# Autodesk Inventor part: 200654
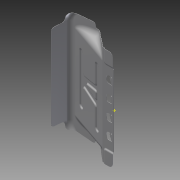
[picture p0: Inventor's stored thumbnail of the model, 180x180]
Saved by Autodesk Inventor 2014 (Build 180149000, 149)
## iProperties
Created: 2007-10
Part Number: 200654
Document SubType Name: Modeling
Designer: TH
Density: 7.85 g/cm^3
Mass: 777.491 g
Surface Area: 2126.93 cm^2
Volume: 99.0434 cm^3
Material: Steel
Description: FRONT TOP SHEILD
Appearance: Steel
Component Category: Lower Component
Author: TH
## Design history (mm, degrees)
sketch "Sketch2"
  geometry: L1 (123, -53.413)-(83.897, -53.413); L2 (83.897, -53.413)-(19.269, -0.007); L3 (-95.471, -64.758)-(-89.791, -0.007); L4 (-89.791, -0.007)-(77.432, -0.007); L5 (-95.471, -64.758)-(-75.394, -64.758); L6 (124.496, -53.413)-(124.496, -54.413); L7 (0, 12.952)-(0, -77.71) reference; L8 (-139.464, 0)-(168.489, 0) reference; L9 (123, -57.413)-(-74.75, -57.413); L10 (-74.75, -57.413)-(-75.394, -64.758); L11 (123, -53.413)-(123, -57.413); 2 further points
  constraints: 18 end point, 4 parallel, 3 perpendicular, 2 point on line, 1 other
  dimensions: "d0" = 89.79065 distance of L3.end point (0, 0); "d1" = 19.26881 distance of L2.end point (0, 0); "d2" = 140.431 deg angle of L2 L4; "d3" = 83.8971 horizontal distance of L1.end point (0, 0); "d4" = 53.41295 distance from line of L1 point (0, 0); "d38" = 20 distance between parallel lines of L10 L3; "d66" = 4 distance from line of L9 L1.end; "d70" = 123 distance from line of point (0, 0) L11
extrude "Extrusion1" new body sketch "Sketch2" stored distance "d6" = 435; taper "d7" = 0 deg
sketch "Sketch3"
  geometry: L1 (0, 0)-(109.059, 0) reference; L2 (0, 0)-(0, 435) reference; L3 (0, 0)-(87.291, 0); L4 (87.291, 0)-(-10, 7.657); L5 (187.801, 317.5)-(199.791, 317.5); L6 (-10, 7.657)-(-10, 0); L7 (-10, 0)-(0, 0); 4 further points
  constraints: 10 end point, 5 point on line, 2 perpendicular, 1 parallel
  dimensions: "d8" = 155 vertical distance of point (0, 62.5) point (89.791, 217.5); "d10" = 2.5 horizontal distance of point (89.791, 217.5) L3.end; "d14" = 100 distance from line of point (89.791, 217.5) L5; "d71" = 10 distance of L6.end L1.start; "d72" = 4.5 deg angle of L1 L4
extrude "Extrusion2" cut sketch "Sketch3" stored distance "d12" = 387.01949; taper "d13" = 0 deg
chamfer "Chamfer1" distance "d16" = 34; stored, may be unused: second distance "d17" = 30, angle "d18" = 45 deg
mirror "Mirror1"
sketch "Sketch4"
  geometry: L1 (83.897, -53.413)-(-71.79, 0); L2 (0, 0)-(-71.79, 0); L3 (130, -53.413)-(83.897, -53.413); L4 (130, -53.413)-(130, 0); L5 (130, 0)-(0, 0)
  constraints: 10 end point, 2 perpendicular, 1 horizontal, 1 parallel
  dimensions: "d19" = 53.41295 distance from line of L2.start L3; "d20" = 83.8971 horizontal distance of L2.start L1.start; "d21" = 71.78981 distance of L2.start L1.end; "d22" = 130 distance from line of L2.start L4
extrude "Extrusion3" cut sketch "Sketch4" stored distance "d23" = 328; taper "d24" = 0 deg
chamfer "Chamfer2" distance "d25" = 29.543; stored, may be unused: second distance "d26" = 15, angle "d27" = 45 deg
chamfer "Chamfer3" distance "d28" = 29.543; stored, may be unused: second distance "d29" = 15, angle "d30" = 45 deg
fillet "Fillet3" dims "d33" = 20
fillet "Fillet8" dims "d40" = 20
fillet "Fillet9" dims "d41" = 20
fillet "Fillet10" dims "d42" = 15, "d58" = 50
fillet "Fillet13" dims "d73" = 2.5
fillet "Fillet14" dims "d74" = 5
shell "Shell1" dims "d43" = 1
sketch "Sketch5"
  geometry: L1 (103, 184)-(6.165, 192.898); L2 (-162.2, 0)-(147.2, 0) reference; L3 (-4.75, 182.94)-(-4.75, 181); L4 (-8.75, 177)-(-46.251, 177); L5 (-49.846, 179.247)-(-50.825, 181.253); L6 (-54.42, 183.5)-(-130, 183.5); L7 (-130, 183.5)-(-130, 220); L8 (-130, 220)-(103, 220); L9 (103, 220)-(103, 184); A1 r 10 centre (5.25, 182.94) between (6.165, 192.898) and (-4.75, 182.94); A2 r 4 centre (-8.75, 181) between (-8.75, 177) and (-4.75, 181); A3 r 4 centre (-46.251, 181) between (-49.846, 179.247) and (-46.251, 177); A4 r 4 centre (-54.42, 179.5) between (-50.825, 181.253) and (-54.42, 183.5); 3 further points
  constraints: 16 end point, 8 point on circle, 8 tangent, 4 centre point, 4 perpendicular, 4 point on line, 2 equal radius, 2 parallel
  dimensions: "d44" = 184 vertical distance of L1.start point (0, 0); "d45" = 103 horizontal distance of point (0, 0) L1.start; "d46" = 5.25 deg angle of L2 L1; "d47" = 4.75 distance from line of L3 point (0, 0); "d48" = 177 distance from line of point (0, 0) L4; "d49" = 44 distance of point (-4.75, 177) point (-48.75, 177); "d50" = 116 deg angle of L4 L5; "d51" = 6.5 distance between parallel lines of L4 L6; "d52" = 130 distance from line of L7 point (0, 0); "d53" = 220 distance between parallel lines of L2 L8; "d54" = 10 radius of A1; "d55" = 4 radius of A2
extrude "Extrusion4" cut sketch "Sketch5" stored distance "d56" = 300; taper "d57" = 0 deg
sketch "Sketch6"
  geometry: L1 (335.141, 0)-(334.789, -51.258) reference; L2 (334.789, -51.258)-(335.036, -15.258); L3 (345.105, -5.327)-(372.105, -5.513); L4 (372.105, -5.513)-(371.789, -51.513); L5 (371.789, -51.513)-(334.789, -51.258); A1 r 10 centre (345.036, -15.327) between (345.105, -5.327) and (335.036, -15.258); 2 further points
  constraints: 8 end point, 3 point on line, 2 perpendicular, 2 point on circle, 2 tangent, 1 centre point, 1 parallel
  dimensions: "d59" = 46 vertical distance of L3.end L4.end; "d60" = 37 horizontal distance of point (335.105, -5.258) L3.end; "d61" = 10 radius of A1
extrude "Extrusion5" cut sketch "Sketch6" distance "d62" = 25; taper "d63" = 0 deg
fillet "Fillet11" dims "d64" = 10
fillet "Fillet12" dims "d65" = 10
mirror "Mirror2"
sketch "Sketch8"
  geometry: L1 (38.269, 329.252)-(0.065, 329.252) reference; L2 (0.065, -37.748)-(38.269, -37.748) reference; L3 (38.269, -37.748)-(38.269, 329.252) reference; L4 (8.269, 329.252)-(8.269, 283.252); L5 (8.269, 283.252)-(37.269, 283.252); L6 (37.269, 283.252)-(37.269, 8.252); L7 (37.269, 8.252)-(8.269, 8.252); L8 (8.269, 8.252)-(8.269, -37.748); 1 further point
  constraints: 10 end point, 3 parallel, 2 perpendicular, 2 point on line, 1 collinear
  dimensions: "d75" = 1 distance between parallel lines of L3 L6; "d76" = 46 distance between parallel lines of L1 L5; "d77" = 46 distance between parallel lines of L2 L7 (= d76); "d78" = 30 distance between parallel lines of L3 L8
extrude "Extrusion7" cut sketch "Sketch8" stored distance "d79" = 275; taper "d80" = 0 deg
sketch "Sketch9"
  geometry: L1 (0.065, -37.748)-(8.269, -37.748) reference; L2 (8.269, -37.748)-(8.269, 8.252) reference; L3 (8.269, 8.252)-(37.269, 8.252) reference; L4 (37.269, 283.252)-(37.269, 8.252) reference; L5 (7.269, -37.748)-(7.269, 9.252); L6 (7.269, 9.252)-(37.269, 9.252); 1 further point
  constraints: 4 end point, 2 point on line, 1 parallel, 1 perpendicular
  dimensions: "d81" = 1 distance between parallel lines of L5 L2; "d82" = 1 distance between parallel lines of L6 L3
extrude "Extrusion8" join sketch "Sketch9" distance "d83" = 3.3941; taper "d84" = 0 deg
sketch "Sketch10"
  geometry: L1 (7.269, 9.252)-(37.269, 9.252) reference; L2 (7.269, -37.748)-(7.269, 9.252) reference; L3 (37.269, 9.252)-(7.269, 9.252); L4 (7.269, 9.252)-(7.269, -37.748); L5 (7.269, -37.748)-(37.269, -37.748); L6 (37.269, -37.748)-(37.269, 9.252); 1 further point
  constraints: 8 end point, 2 parallel, 1 horizontal, 1 perpendicular
extrude "Extrusion9" join sketch "Sketch10" distance "d85" = 1; taper "d86" = 0 deg
mirror "Mirror4"
fillet "Fillet15" dims "d87" = 5, "d88" = 6
fillet "Fillet16" dims "d89" = 4.75, "d90" = 5.75
sketch "Sketch12"
  geometry: L1 (0.307, -1)-(264.202, -1) reference; L2 (315.755, -4.394)-(271.933, -4.394) reference; L3 (315.755, -4.394)-(315.755, -3.394) reference; L4 (315.755, -3.394)-(272.24, -3.394) reference; L5 (0, 0)-(264.51, 0) reference; L6 (-51.245, -3.394)-(-7.73, -3.394) reference; L7 (-51.245, -4.394)-(-51.245, -3.394) reference; L8 (-51.245, -4.394)-(-7.423, -4.394) reference; A1 r 5.75 centre (-7.423, 1.356) between (-7.423, -4.394) and (-3.19, -2.535) reference; A2 r 4.75 centre (0.307, -5.75) between (0.307, -1) and (-3.19, -2.535) reference; A3 r 4.75 centre (264.202, -5.75) between (267.699, -2.535) and (264.202, -1) reference; A4 r 5.75 centre (271.933, 1.356) between (267.699, -2.535) and (271.933, -4.394) reference; A5 r 4.75 centre (272.24, 1.356) between (268.743, -1.859) and (272.24, -3.394) reference; A6 r 5.75 centre (264.51, -5.75) between (268.743, -1.859) and (264.51, 0) reference; A7 r 5.75 centre (0, -5.75) between (0, 0) and (-4.233, -1.859) reference; A8 r 4.75 centre (-7.73, 1.356) between (-7.73, -3.394) and (-4.233, -1.859) reference; 1 further point
extrude "Extrusion11" join sketch "Sketch12" distance "d93" = 2.5; taper "d94" = 0 deg
fillet "Fillet17" dims "d95" = 15
sketch "Sketch13"
  geometry: L1 (34.048, 44.224)-(34.048, 44.224); L2 (34.048, 229.224)-(34.048, 229.224); L3 (26.548, 221.724)-(26.548, 51.724); L4 (127.048, 29.224)-(127.048, 29.224); L5 (134.548, 36.724)-(134.548, 236.724); L6 (127.048, 244.224)-(127.048, 244.224); L7 (53.436, 119.438)-(111.436, 108.284); L8 (53.436, 154.011)-(111.436, 165.164); L9 (41.548, 136.724)-(119.548, 136.724); L10 (119.548, 166.847)-(119.548, 166.724); L11 (119.548, 106.724)-(119.548, 106.602); L12 (119.548, 236.724)-(119.548, 174.985); L13 (119.548, 98.464)-(119.548, 36.724); L14 (41.548, 51.724)-(41.548, 109.618); L15 (41.548, 163.831)-(41.548, 221.724); L16 (157.597, 0)-(0, 0) reference; L17 (68.509, 131.814)-(113.603, 123.142); L18 (119.548, 128.052)-(119.548, 145.396); L19 (113.603, 150.306)-(68.509, 141.634); A1 r 7.5 centre (34.048, 51.724) between (26.548, 51.724) and (34.048, 44.224); A2 r 7.5 centre (34.048, 51.724) between (34.048, 44.224) and (41.548, 51.724); A3 r 7.5 centre (127.048, 36.724) between (119.548, 36.724) and (127.048, 29.224); A4 r 7.5 centre (127.048, 36.724) between (127.048, 29.224) and (134.548, 36.724); A5 r 7.5 centre (127.048, 236.724) between (127.048, 244.224) and (119.548, 236.724); A6 r 7.5 centre (127.048, 236.724) between (134.548, 236.724) and (127.048, 244.224); A7 r 7.5 centre (34.048, 221.724) between (41.548, 221.724) and (34.048, 229.224); A8 r 7.5 centre (34.048, 221.724) between (34.048, 229.224) and (26.548, 221.724); A9 r 10 centre (51.548, 109.618) between (53.436, 119.438) and (41.548, 109.618); A10 r 10 centre (51.548, 163.831) between (41.548, 163.831) and (53.436, 154.011); A11 r 10 centre (109.548, 98.464) between (119.548, 98.464) and (111.436, 108.284); A12 r 10 centre (109.548, 174.985) between (111.436, 165.164) and (119.548, 174.985); A13 r 5 centre (69.453, 136.724) between (68.509, 141.634) and (68.509, 131.814); A14 r 5 centre (114.548, 145.396) between (119.548, 145.396) and (113.603, 150.306); A15 r 5 centre (114.548, 128.052) between (113.603, 123.142) and (119.548, 128.052); 4 further points
  constraints: 36 end point, 34 tangent, 30 point on circle, 15 centre point, 12 equal radius, 12 point on line, 8 parallel, 6 perpendicular, 2 horizontal
  dimensions: "d96" = 185 distance of point (26.548, 229.224) point (26.548, 44.224); "d104" = 70 distance from line of L5 point (64.548, 136.724); "d105" = 108 distance between parallel lines of L5 L3; "d106" = 7.5 radius of A1; "d109" = 200 distance of A6.centre A3.centre; "d110" = 10 radius of A9; "d111" = 27.10631 distance from line of L9 A9.centre; "d112" = 27.10631 distance from line of A10.centre L9; "d113" = 38.26016 distance from line of L9 A11.centre; "d114" = 38.26016 distance from line of A12.centre L9; "d115" = 55 distance from line of point (64.548, 136.724) L12; "d116" = 23 distance from line of point (64.548, 136.724) L15; "d117" = 92.5 distance from line of L9 point (26.548, 229.224) (derived); "d118" = 100 distance from line of L9 A5.centre; "d148" = 15 distance between parallel lines of L7 L17; "d150" = 15 distance between parallel lines of L5 L18; "d151" = 5 radius of A13
extrude "Extrusion12" cut sketch "Sketch13" distance "d119" = 1; taper "d120" = 0 deg
sketch "Sketch14"
  geometry: L1 (26.548, 51.724)-(26.548, 221.724) reference; L2 (41.548, 221.724)-(41.548, 163.831) reference; L3 (53.436, 154.011)-(111.436, 165.164) reference; L4 (119.548, 174.985)-(119.548, 236.724) reference; L5 (134.548, 236.724)-(134.548, 36.724) reference; L6 (119.548, 36.724)-(119.548, 98.464) reference; L7 (111.436, 108.284)-(53.436, 119.438) reference; L8 (41.548, 109.618)-(41.548, 51.724) reference; L9 (25.548, 221.724)-(25.548, 51.724); L10 (42.548, 51.724)-(42.548, 109.618); L11 (53.247, 118.456)-(111.247, 107.302); L12 (118.548, 98.464)-(118.548, 36.724); L13 (135.548, 36.724)-(135.548, 236.724); L14 (118.548, 236.724)-(118.548, 174.985); L15 (111.247, 166.147)-(53.247, 154.993); L16 (42.548, 163.831)-(42.548, 221.724); L17 (68.509, 131.814)-(113.603, 123.142) reference; L18 (119.548, 128.052)-(119.548, 145.396) reference; L19 (113.603, 150.306)-(68.509, 141.634) reference; L20 (68.698, 140.652)-(113.792, 149.324); L21 (118.548, 145.396)-(118.548, 128.052); L22 (113.792, 124.124)-(68.698, 132.796); A1 r 7.5 centre (34.048, 51.724) between (26.548, 51.724) and (41.548, 51.724) reference; A2 r 7.5 centre (34.048, 221.724) between (41.548, 221.724) and (26.548, 221.724) reference; A3 r 10 centre (51.548, 163.831) between (41.548, 163.831) and (53.436, 154.011) reference; A4 r 10 centre (109.548, 174.985) between (111.436, 165.164) and (119.548, 174.985) reference; A5 r 7.5 centre (127.048, 236.724) between (134.548, 236.724) and (119.548, 236.724) reference; A6 r 7.5 centre (127.048, 36.724) between (119.548, 36.724) and (134.548, 36.724) reference; A7 r 10 centre (109.548, 98.464) between (119.548, 98.464) and (111.436, 108.284) reference; A8 r 10 centre (51.548, 109.618) between (53.436, 119.438) and (41.548, 109.618) reference; A9 r 8.5 centre (34.048, 51.724) between (25.548, 51.724) and (42.548, 51.724); A10 r 9 centre (51.548, 109.618) between (53.247, 118.456) and (42.548, 109.618); A11 r 9 centre (109.548, 98.464) between (118.548, 98.464) and (111.247, 107.302); A12 r 8.5 centre (127.048, 36.724) between (118.548, 36.724) and (135.548, 36.724); A13 r 8.5 centre (127.048, 236.724) between (135.548, 236.724) and (118.548, 236.724); A14 r 9 centre (109.548, 174.985) between (111.247, 166.147) and (118.548, 174.985); A15 r 9 centre (51.548, 163.831) between (42.548, 163.831) and (53.247, 154.993); A16 r 8.5 centre (34.048, 221.724) between (42.548, 221.724) and (25.548, 221.724); A17 r 5 centre (114.548, 128.052) between (113.603, 123.142) and (119.548, 128.052) reference; A18 r 5 centre (114.548, 145.396) between (119.548, 145.396) and (113.603, 150.306) reference; A19 r 5 centre (69.453, 136.724) between (68.509, 141.634) and (68.509, 131.814) reference; A20 r 4 centre (114.548, 145.396) between (118.548, 145.396) and (113.792, 149.324); A21 r 4 centre (114.548, 128.052) between (113.792, 124.124) and (118.548, 128.052); A22 r 4 centre (69.453, 136.724) between (68.698, 140.652) and (68.698, 132.796); 1 further point
  constraints: 22 end point, 22 point on circle, 11 centre point, 20 other
  dimensions: "d121" = 1 distance between parallel lines of L1 L9; "d152" = 1 distance between parallel lines of L17 L22 (derived)
extrude "Extrusion13" join sketch "Sketch14" distance "d122" = 4; taper "d123" = 0 deg
sketch "Sketch20"
  geometry: L1 (68.509, -131.814)-(113.603, -123.142) reference; L2 (119.548, -128.052)-(119.548, -145.396) reference; L3 (113.603, -150.306)-(68.509, -141.634) reference; L4 (26.548, -51.724)-(26.548, -221.724) reference; L5 (41.548, -221.724)-(41.548, -163.831) reference; L6 (53.436, -154.011)-(111.436, -165.164) reference; L7 (119.548, -174.985)-(119.548, -236.724) reference; L8 (134.548, -236.724)-(134.548, -36.724) reference; L9 (119.548, -36.724)-(119.548, -98.464) reference; L10 (111.436, -108.284)-(53.436, -119.438) reference; L11 (41.548, -109.618)-(41.548, -51.724) reference; A1 r 5 centre (114.548, -128.052) between (119.548, -128.052) and (113.603, -123.142) reference; A2 r 5 centre (114.548, -145.396) between (113.603, -150.306) and (119.548, -145.396) reference; A3 r 5 centre (69.453, -136.724) between (68.509, -131.814) and (68.509, -141.634) reference; A4 r 7.5 centre (34.048, -221.724) between (26.548, -221.724) and (41.548, -221.724) reference; A5 r 10 centre (51.548, -163.831) between (53.436, -154.011) and (41.548, -163.831) reference; A6 r 10 centre (109.548, -174.985) between (119.548, -174.985) and (111.436, -165.164) reference; A7 r 7.5 centre (127.048, -236.724) between (119.548, -236.724) and (134.548, -236.724) reference; A8 r 7.5 centre (127.048, -36.724) between (134.548, -36.724) and (119.548, -36.724) reference; A9 r 10 centre (109.548, -98.464) between (111.436, -108.284) and (119.548, -98.464) reference; A10 r 10 centre (51.548, -109.618) between (41.548, -109.618) and (53.436, -119.438) reference; A11 r 7.5 centre (34.048, -51.724) between (41.548, -51.724) and (26.548, -51.724) reference; 1 further point
extrude "Extrusion17" cut sketch "Sketch20" distance "d173" = 3; taper "d174" = 0 deg
fillet "Fillet18" dims "d124" = 5, "d125" = 4
sketch "Sketch15" dims "d137" = 10, "d144" = 10
  geometry: L1 (39.769, 13.497)-(39.769, 278.007) reference; L2 (33.769, 102.752)-(17.277, 102.752); L3 (17.277, 128.752)-(33.769, 128.752); L4 (33.769, 128.752)-(33.769, 102.752); L5 (33.769, 115.752)-(12.769, 115.752); L6 (83.763, 145.752)-(-224.196, 145.752) reference; L7 (33.769, 42.752)-(17.277, 42.752); L8 (33.769, 55.752)-(12.769, 55.752); L9 (17.277, 68.752)-(33.769, 68.752); L10 (33.769, 68.752)-(33.769, 42.752); L11 (17.277, 188.752)-(33.769, 188.752); L12 (33.769, 175.752)-(12.769, 175.752); L13 (33.769, 162.752)-(17.277, 162.752); L14 (33.769, 188.752)-(33.769, 162.752); L15 (17.277, 248.752)-(33.769, 248.752); L16 (33.769, 235.752)-(12.769, 235.752); L17 (33.769, 222.752)-(17.277, 222.752); L18 (33.769, 248.752)-(33.769, 222.752); A1 r 21 centre (33.769, 115.752) between (17.277, 128.752) and (17.277, 102.752); A2 r 21 centre (33.769, 55.752) between (17.277, 68.752) and (17.277, 42.752); A3 r 21 centre (33.769, 175.752) between (17.277, 188.752) and (17.277, 162.752); A4 r 21 centre (33.769, 235.752) between (17.277, 248.752) and (17.277, 222.752); 1 further point
  constraints: 32 end point, 12 point on circle, 4 centre point, 4 coincident, 2 vertical, 1 horizontal, 1 midpoint, 1 parallel, 36 other
  dimensions: "d126" = 26 distance of L3.end L2.start; "d128" = 30 distance between parallel lines of L5 L6; "d129" = 21 distance of L5.start L5.end; "d130" = 13 distance between parallel lines of L2 L5 (derived); "d131" = 6 distance from line of L1 A1.centre; "d134" = 60 distance of L2.end L7.end; "d141" = 60 distance of L3.end L11.end
extrude "Extrusion14" cut sketch "Sketch15" distance "d146" = 1; taper "d147" = 0 deg
fillet "Fillet19" dims "d153" = 8
workplane "Work Plane1"
sketch "Sketch17"
  geometry: L1 (0, 1)-(0, 0) reference; L2 (0, 1)-(-2.283, 1); L3 (-4.827, 2.41)-(-6.911, 5.745); L4 (-9.746, 7.586)-(-15.54, 8.401); L5 (-15.54, 8.401)-(-15.679, 7.41); L6 (-15.679, 7.41)-(-9.885, 6.596); L7 (-7.759, 5.215)-(-5.675, 1.88); L8 (-2.283, 0)-(0, 0); A1 r 3 centre (-10.303, 3.625) between (-7.759, 5.215) and (-9.885, 6.596); A2 r 3 centre (-2.283, 4) between (-4.827, 2.41) and (-2.283, 1); A3 r 4 centre (-10.303, 3.625) between (-6.911, 5.745) and (-9.746, 7.586); A4 r 4 centre (-2.283, 4) between (-5.675, 1.88) and (-2.283, 0); 3 further points
  constraints: 14 end point, 8 point on circle, 8 tangent, 4 centre point, 4 point on line, 3 perpendicular, 2 equal radius, 2 parallel
  dimensions: "d154" = 1 distance between parallel lines of L7 L3; "d155" = 1 distance between parallel lines of L4 L6; "d156" = 4.5 distance of L1.end point (-4.5, 0); "d157" = 58 deg angle of L3 L2; "d158" = 50 deg angle of L6 L7; "d159" = 8.5 distance from line of L1 point (-8.5, 6.401); "d160" = 7.25 distance of L5.end point (-8.5, 6.401); "d161" = 3 radius of A1; "d162" = 4 radius of A3
extrude "Extrusion15" join sketch "Sketch17" stored distance "d163" = 20; taper "d164" = 0 deg
sketch "Sketch18"
  geometry: L1 (-5.851, 0)-(0, 0) reference; L2 (0, 20)-(-5.851, 20) reference; L3 (-5.851, 0)-(-5.851, 20) reference; L4 (-5.851, 10)-(14.149, 10); A1 r 20 centre (14.149, 10) between (-3.172, 20) and (-3.172, 0); 1 further point
  constraints: 3 point on circle, 2 end point, 2 point on line, 1 centre point, 1 coincident, 1 midpoint, 1 perpendicular
  dimensions: "d165" = 40 diameter of A1
extrude "Extrusion16" cut sketch "Sketch18" distance "d166" = 1; taper "d167" = 0 deg
pattern_linear "Rectangular Pattern1"
fillet "Fillet20" dims "d168" = 4
fillet "Fillet21" dims "d169" = 2
sketch "Sketch19"
  geometry: L1 (-89.995, -13.784)-(-94.467, -64.758) reference; L2 (-94.467, -64.758)-(-95.471, -64.758) reference; L3 (-95.471, -64.758)-(-90.992, -13.696) reference; L4 (-76.049, -0.007)-(-75.105, -0.007) reference; L5 (-68.615, -1.089)-(-46.894, -8.541) reference; L6 (-38.518, -7.186)-(-10.039, -16.956) reference; L7 (-4.259, -23.168)-(41.073, -38.721) reference; L8 (49.449, -37.366)-(56.262, -39.703) reference; L9 (62.042, -45.915)-(83.108, -53.142) reference; L10 (84.731, -53.413)-(124.5, -53.413) reference; L11 (124.5, -53.413)-(124.5, -54.413) reference; L12 (124.5, -54.413)-(84.731, -54.413) reference; L13 (82.784, -54.088)-(62.961, -47.287) reference; L14 (-48.462, -9.061)-(-68.939, -2.035) reference; L15 (-75.105, -1.007)-(-76.049, -1.007) reference; L16 (57.181, -41.075)-(49.22, -38.344) reference; L17 (40.844, -39.7)-(-4.679, -24.082) reference; L18 (-10.459, -17.87)-(-40.086, -7.705) reference; L19 (124.5, -53.413)-(124.5, -54.413); L20 (124.5, -53.413)-(124.75, -53.413); L21 (124.5, -54.413)-(124.75, -54.413); L22 (124.75, -54.513)-(123.25, -54.513); L23 (123.25, -54.513)-(123.25, -55.513); L24 (124.75, -54.463)-(124.75, -55.513); L25 (124.75, -55.513)-(123.25, -55.513); A1 r 14 centre (-76.049, -15.007) between (-76.049, -1.007) and (-89.995, -13.784) reference; A2 r 15 centre (-76.049, -15.007) between (-76.049, -0.007) and (-90.992, -13.696) reference; A3 r 20 centre (-75.105, -20.007) between (-68.615, -1.089) and (-75.105, -0.007) reference; A4 r 4 centre (-45.596, -4.758) between (-46.894, -8.541) and (-43.171, -7.939) reference; A5 r 5 centre (-40.14, -11.916) between (-38.518, -7.186) and (-43.171, -7.939) reference; A6 r 5 centre (-11.662, -21.686) between (-6.828, -20.408) and (-10.039, -16.956) reference; A7 r 4 centre (-2.961, -19.385) between (-6.828, -20.408) and (-4.259, -23.168) reference; A8 r 4 centre (42.371, -34.937) between (41.073, -38.721) and (44.796, -38.119) reference; A9 r 5 centre (47.827, -42.095) between (49.449, -37.366) and (44.796, -38.119) reference; A10 r 5 centre (54.639, -44.432) between (59.473, -43.154) and (56.262, -39.703) reference; A11 r 4 centre (63.34, -42.131) between (59.473, -43.154) and (62.042, -45.915) reference; A12 r 5 centre (84.731, -48.413) between (83.108, -53.142) and (84.731, -53.413) reference; A13 r 6 centre (84.731, -48.413) between (82.784, -54.088) and (84.731, -54.413) reference; A14 r 5 centre (64.584, -42.558) between (59.75, -43.836) and (62.961, -47.287) reference; A15 r 19 centre (-75.105, -20.007) between (-68.939, -2.035) and (-75.105, -1.007) reference; A16 r 4 centre (55.883, -44.859) between (59.75, -43.836) and (57.181, -41.075) reference; A17 r 4 centre (47.922, -42.128) between (49.22, -38.344) and (45.498, -38.947) reference; A18 r 5 centre (42.467, -34.97) between (40.844, -39.7) and (45.498, -38.947) reference; A19 r 5 centre (-3.056, -19.352) between (-7.89, -20.63) and (-4.679, -24.082) reference; A20 r 4 centre (-11.757, -21.653) between (-7.89, -20.63) and (-10.459, -17.87) reference; A21 r 4 centre (-41.384, -11.489) between (-40.086, -7.705) and (-43.808, -8.308) reference; A22 r 5 centre (-46.839, -4.331) between (-48.462, -9.061) and (-43.808, -8.308) reference; A23 r 0.05 centre (124.75, -54.463) between (124.75, -54.413) and (124.75, -54.513); A24 r 1.05 centre (124.75, -54.463) between (124.75, -55.513) and (124.75, -53.413); 1 further point
  constraints: 14 end point, 6 tangent, 4 point on circle, 2 centre point, 2 parallel, 2 perpendicular, 1 coincident, 1 collinear, 1 point on line
  dimensions: "d179" = 0.25 distance from line of L11 A23.centre; "d180" = 0.1 diameter of A23; "d181" = 1.5 distance of L22.start L22.end
extrude "Extrusion18" join sketch "Sketch19" stored distance "d177" = 263; taper "d178" = 0 deg
fillet "Fillet22" dims "d182" = 0.25
workpoint "Work Point1"
body "Solid1"
node "Project Cut Edges1"
other parameters: "d107" = 15, "d108" = 15
